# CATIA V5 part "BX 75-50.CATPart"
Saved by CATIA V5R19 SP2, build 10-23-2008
Part number: BX 75-50
Bounding box of the stored display mesh (mm): x -15.868 to 15.868, y -15.868 to 15.868, z 0 to 195
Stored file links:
  C:\Users\Bora\Desktop\3D Katı model\BX serisi\BX 75\BX 75-50.CATPart
  C:\Program Files\Dassault Systemes\B19\intel_a\reffiles\standard\MetricThickPitch.txt
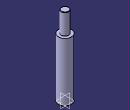
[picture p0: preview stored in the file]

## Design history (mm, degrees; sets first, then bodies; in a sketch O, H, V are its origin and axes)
Body1 (main body)
  Sketch1 on yz-plane, origin (0, 0, 0), H (0, 1, 0), V (0, 0, 1)
    point P1 (9.5, 194)
    point P3 (9.5, 194)
    arc A1 centre (8.5, 194) radius 1 from (9.5, 194) to (8.5, 195) ccw
    line L1 (9.5, 194) -> (9.5, 144)
    line L2 (16, 144) -> (16, 0)
    line L3 (16, 0) -> (0, 0)
    line L4 (16, 144) -> (9.5, 144)
    line L5 (8.5, 195) -> (0, 195)
    point P7 (0, 195)
    horizontal: L3 H, L4 H
    coincidence: P7 V, P1 P3
    tangency: L5 A1
  Shaft1: profile Sketch1, axis Sketch1.V, angle 360
  Sketch2 on face of Shaft1 from Sketch1.L3, origin (0, 0, 0), H (1, 0, 0), V (0, -1, 0)
    point P1 (7.5, 0)
    distance P1 V = 7.5
  Hole1: placed by Sketch2, at (7.5, 0, 0) direction (0, 0, 1), diameter 3.242, depth 5, threaded "M4", thread diameter 4, thread depth 5, pitch 0.7
  Sketch3 on face of Shaft1 from Sketch1.L3, origin (0, 0, 0), H (1, 0, 0), V (0, -1, 0)
    point P1 (-7.5, 0)
    distance P1 V = 7.5
  Hole2: placed by Sketch3, at (-7.5, 0, 0) direction (0, 0, 1), diameter 3.242, depth 5, threaded "M4", thread diameter 4, thread depth 5, pitch 0.7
